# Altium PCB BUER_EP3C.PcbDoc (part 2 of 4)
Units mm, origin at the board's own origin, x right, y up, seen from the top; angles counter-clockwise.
Board outline 150 x 80 mm, 2 copper layers (Top Layer, Bottom Layer), stack 1.571 mm thick; 295 components, 180 nets, 1344 pads, 488 vias.
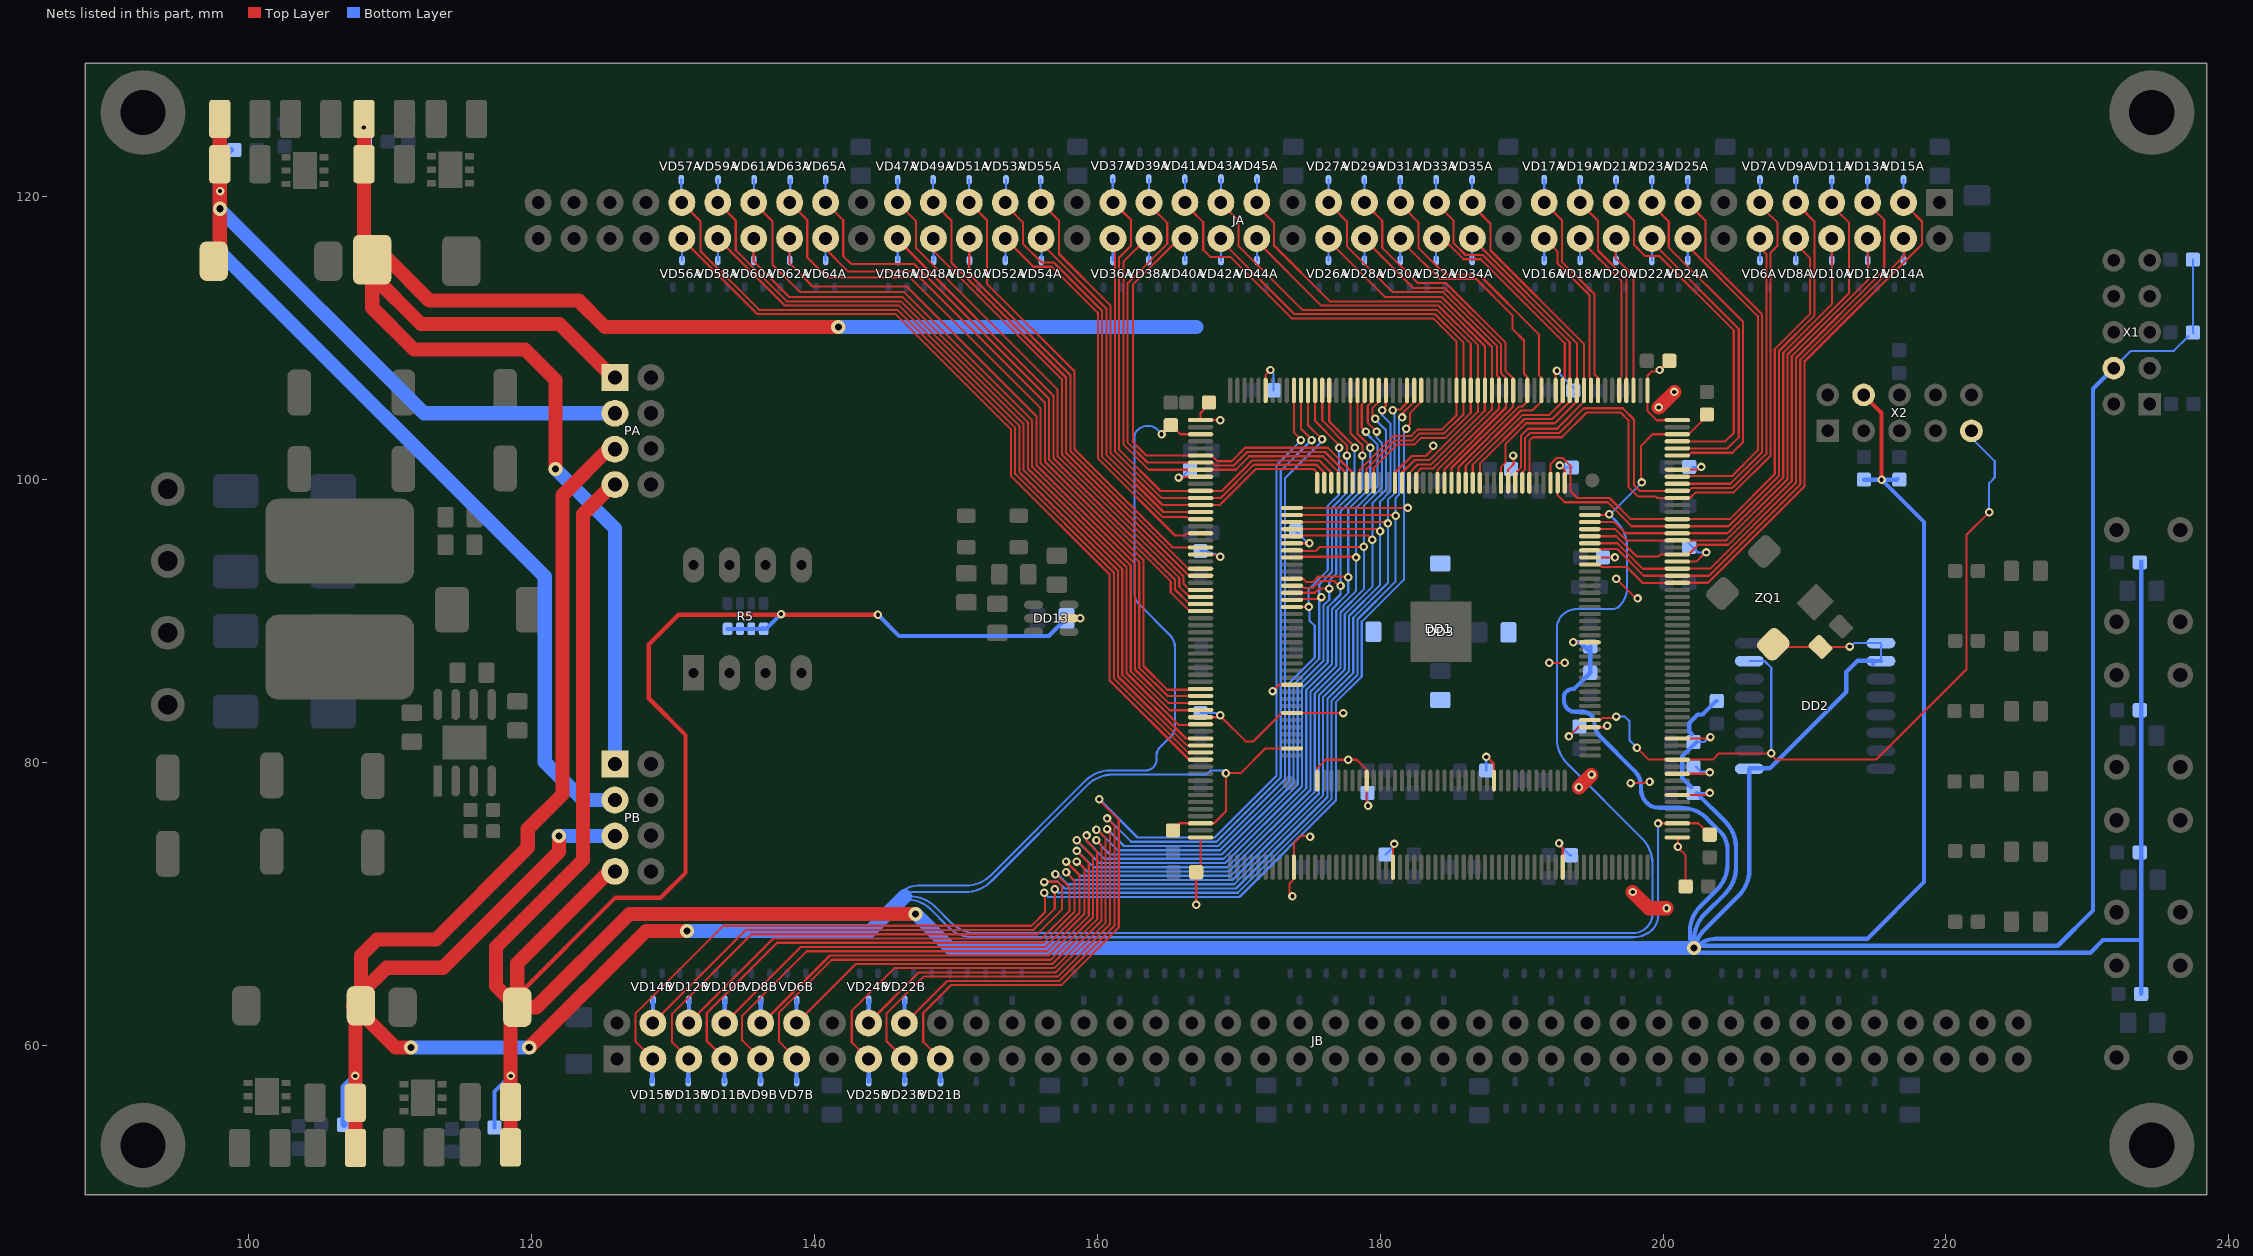
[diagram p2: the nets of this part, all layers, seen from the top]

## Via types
v1: diameter 0.6, hole 0.3, Top Layer to Bottom Layer, tented both sides, 413 vias
v2: diameter 1.4, hole 0.7, Top Layer to Bottom Layer, 32 vias
v3: diameter 1, hole 0.5, Top Layer to Bottom Layer, tented both sides, 19 vias
v4: diameter 0.66, hole 0.33, Top Layer to Bottom Layer, tented top, 16 vias
v5: diameter 0.6, hole 0.3, Top Layer to Bottom Layer, 8 vias

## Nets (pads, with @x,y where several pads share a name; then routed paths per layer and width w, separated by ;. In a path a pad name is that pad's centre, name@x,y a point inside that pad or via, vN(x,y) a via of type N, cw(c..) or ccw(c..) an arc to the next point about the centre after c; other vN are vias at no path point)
1.2V: C21.1 C22.1 C23.1 C24.1 C25.1 C26.1 C27.1 C28.1 C29.1 C30.1 C31.1 C32.1 C34.1 C35.1 C47.1 C75.1 C76.1 C77.1 C78.1 C79.1 C80.1 C81.1 C82.1 C86.1 C87.1 C88.1 C89.1 DD1.1 DD1.10 DD1.40 DD1.53 DD1.60 DD1.61 DD1.74 DD1.115 DD1.121 DD1.129 DD1.140 DD1.163 DD1.180 DD1.190 DD1.204 DD1.228 DD3.5 DD3.29 DD3.37 DD3.45 DD3.61 DD3.78 DD3.102 DD3.109 DD3.116 DD3.134 L1.2 PA.1 PB.1 R6.2 | length 242
  Top Layer w0.15: v1@165.9,100 cw(c166.399,99.501) 166.399,100.207 DD1.129@167.306,100.207 ; v1@167,69.9 C32.1@167,72.25 167.306,72.25 DD1.180@167.306,74.707 ; DD1.163@167.306,83.207 168.507,83.207 v1@168.65,83.35 ; DD1.140@167.306,94.707 168.08,94.707 cw(c168.08,93.83) v1@168.7,94.45 ; DD1.121@167.306,104.157 DD1.121@167.306,104.207 ; C29.1@167.65,105.8 167.65,105.049 167.306,104.705 DD1.121@167.306,104.207 ; v1@168.65,104.15 168.593,104.207 DD1.121@167.306,104.207 ; v1@168.75,83.25 170.5,81.5 171.05,81.5 173.05,83.5 DD3.102@173.775,83.5 v1@177.3,83.5 ; DD1.115@171.906,106.307 171.906,107.406 v1@172.2,107.7 ; DD3.78@173.775,95.5 v1(175,95.5) v1@175.15,95.5 ; v1@173.85,70.5 173.6,70.75 173.6,71.45 173.906,71.756 173.906,74.306 174.4,74.8 v1@175,74.8 ; DD3.109@175.55,78.725 175.55,79.6 176.15,80.2 178.35,80.2 179.05,79.5 DD3.116@179.05,78.725 179.05,77 v1@179.25,76.8 ; DD1.204@180.906,72.607 180.906,74.106 v1@180.95,74.15 ; DD3.61@181.05,99.775 181.05,100.5 182.225,101.675 183.225,101.675 183.75,102.2 v1(183.75,102.4) ; v1@187.55,80.4 188.05,79.9 DD3.134@188.05,78.725 ; DD3.45@189.05,99.775 189.05,100.7 189.45,101.1 v1@189.45,101.75 ; v1@191.9,87.05 v1(191.95,87.05) v1(193.05,87.05) ; DD1.74@192.406,106.307 192.406,107.506 v1@192.6,107.7 ; v1@192.6,74.25 192.906,73.944 DD1.228@192.906,72.607 ; v1(192.7,101) 193.05,100.65 DD3.37@193.05,99.775 ; v1@193.25,81.75 194,82.5 DD3.5@194.825,82.5 195.95,82.5 v1(196.05,82.6) ; DD3.29@194.825,94.5 196.45,94.5 v1@196.5,94.55 ; v1(196.7,93) v1@198.15,91.55 ; v1(197.7,78.55) 198.85,78.55 v1@198.95,78.65 ; C25.1@200.1,108.05 199.7,107.65 199.2,107.65 198.906,107.356 DD1.61@198.906,106.307 198.906,104.844 199.55,104.2 DD1.60@200.4,104.2 ; DD1.10@201.006,79.207 203.207,79.207 v1@203.35,79.35 ; DD1.40@201.006,94.207 202.357,94.207 v1@203,94.85 ; DD1.53@201.006,100.707 202.707,100.707 v1@202.75,100.75 ; DD1.1@201.05,74.7 201.05,74 201.6,73.45 C21.1@201.6,71.25
  Top Layer w1: C34.1@108.175,125.5 C35.1@108.175,122.3 108.175,116.125 L1.2@108.75,115.55 ; L1.2@109,115.3 L1.2@108.75,115.55 ; v3(121.7,100.75) 121.7,107.05 119.55,109.2 111.7,109.2 108.75,112.15 L1.2@108.75,114.45 ; PA.1@125.5,107.5 122,111 112.2,111 L1.2@108.75,114.45 ; v3(141.7,110.8) 125.2,110.8 123.35,112.65 112.8,112.65 109.9,115.55 L1.2@108.75,115.55 ; v1(194.05,78.25) v1@194.9,79.1 ; v1(197.85,70.85) 199,69.7 v1(200.25,69.7) ; v1(199.7,105.1) v1(200.8,106.2) ; L1.2@108.75,114.45 L1.2@108.75,115.55
  Bottom Layer w0.15: v1@165.7,99.9 166.465,100.665 cw(c166.55,100.579) C30.1@166.55,100.7 ; C22.1@167.3,83.5 168.65,83.5 v1@168.75,83.4 ; C31.1@167.3,94.95 167.493,94.95 cw(c167.493,93.243) v1@168.7,94.45 ; v1@172.25,107.7 172.47,107.48 C28.1@172.47,106.315 ; C81.1@174.05,96.35 174.8,95.6 v1@174.85,95.6 ; C75.1@179.1,77.85 179.1,77.15 v1@179.15,77.1 ; C23.1@180.4,73.5 180.95,74.05 v1@180.85,74.15 ; C76.1@187.5,79.45 v1(187.5,80.4) ; v1(192.5,107.7) v1@192.5,107.788 ; v1@192.55,107.6 192.575,107.6 193.875,106.3 cw(c193.453,106.3) C27.1@193.751,106.001 ; v1@192.6,74.25 193.4,73.45 C82.1@193.5,73.45 ; v1(192.7,101) 192.85,100.85 C79.1@193.55,100.85 ; v1@193.25,81.75 193.3,81.75 C77.1@194.1,82.55 ; C78.1@195.75,94.5 196.5,94.5 v1@196.55,94.55 ; C24.1@201.744,95.581 202.475,94.85 v1(203.05,94.85) ; C26.1@202.075,100.9 v1(202.7,100.9) ; C47.1@202.325,79.7 202.375,79.65 202.675,79.35 v1@203.35,79.35
  Bottom Layer w0.5: R6.2@108.1,123.95 108.15,124 v1(108.15,124.9)
  Bottom Layer w1: v3(121.7,100.75) 125.91,96.54 PB.1@125.91,79.89 ; v3(141.7,110.8) 167,110.8
  other v1: 167,69.95 173.8,70.55 201.05,74.05 181,74.25 192.65,74.3 175.05,74.75 179.15,76.95 199.05,78.65 194.95,79.15 203.3,79.3 177.75,80.2 193.35,81.85 168.7,83.35 177.4,83.5 198.2,91.6 196.6,94.5 168.7,94.55 165.75,100.15 189.4,101.7 168.7,104.2 172.25,107.75 199.75,107.75
1.8V: C43.1 C44.1 L2.2 PA.3 PB.3 R17.2 | length 101.4
  Top Layer w1: L2.2@97.8,115.9 97.975,116.075 C44.1@97.975,122.3 C43.1@97.975,125.5
  Bottom Layer w0.4: v1(98,120.4) 98,122.525 R17.2@98.775,123.3
  Bottom Layer w1: v3(98,119.15) v3@98,119.1 ; PA.3@125.9,104.69 112.41,104.69 v3@98,119.1 ; PB.3@125.91,77.35 123.65,77.35 120.95,80.05 120.95,93.15 98,116.1 v3@98,119.1
2.5V: C17.1 C18.1 C19.1 C20.1 C52.1 C53.1 DD1.3 DD1.58 DD1.123 DD1.178 DD3.35 DD3.107 L4.2 PA.5 PB.5 R8.2 | length 385.5
  Top Layer w0.15: v1@164.6,103.2 C19.1@165.165,103.765 ; C19.1@165.165,103.765 ccw(c165.079,103.85) C19.1@165.2,103.85 ; C19.1@165.25,103.45 165.65,103.45 165.893,103.207 DD1.123@167.306,103.207 ; C20.1@165.6,75.5 165.807,75.707 DD1.178@167.306,75.707 168.257,75.707 169.1,76.55 169.1,79.2 169.15,79.25 170.149,79.25 171.899,81 DD3.107@173.2,81 ; DD3.35@194.825,97.5 v1@196.001,97.5 ; v1@198.45,99.85 198.45,102.4 199.257,103.207 201.807,103.207 C18.1@202.8,104.2 ; v1@199.65,75.65 199.707,75.707 DD1.3@201.006,75.707 ; DD1.3@201,75.7 DD1.3@201.006,75.707 ; C17.1@202.9,75.3 202.493,75.707 DD1.3@201.006,75.707
  Top Layer w1: L4.2@107.4,62.75 107.575,62.575 C53.1@107.575,52.75 ; v3(111.5,59.85) 110.4,59.85 107.95,62.3 L4.2@107.95,62.8 L4.2@107.95,63.7 ; v3(119.85,59.85) 128.1,68.1 v3(131,68.1) ; v3@121.95,74.7 121.95,73.7 113.75,65.5 109.75,65.5 L4.2@107.95,63.7 ; PA.5@125.5,102.2 122.2,98.9 122.2,77.75 119.75,75.3 119.75,74 113.25,67.5 109.1,67.5 107.95,66.35 L4.2@107.95,63.7
  Bottom Layer w0.15: 146.2,70.85 cw(c147.286,69.764) 147.286,71.3 150.698,71.3 ccw(c150.698,73.84) 152.494,72.044 159.156,78.706 cw(c160.952,76.91) 160.952,79.45 163.45,79.45 ccw(c163.45,80.174) 163.962,79.662 ccw(c163.388,80.236) 164.2,80.236 164.2,80.496 cw(c165.054,80.496) 164.45,81.1 165.217,81.867 ccw(c164.534,82.55) 165.5,82.55 165.5,88.155 ccw(c164.305,88.155) 165.15,89 162.897,91.253 cw(c163.495,91.85) 162.65,91.85 162.65,103.088 cw(c163.162,103.088) 162.8,103.45 162.832,103.482 cw(c163.6,102.714) 163.6,103.8 cw(c163.6,102.834) 164.283,103.517 v1@164.5,103.3 ; 146.55,70.65 cw(c147.033,70.167) 147.033,70.85 150.698,70.85 ccw(c150.698,73.39) 152.494,71.594 159.306,78.406 cw(c161.102,76.61) 161.102,79.15 ; 146.65,70.3 cw(c146.65,68.127) 148.186,69.664 149.456,68.394 ccw(c151.252,70.19) 151.252,67.65 197.922,67.65 ccw(c197.922,69.528) 199.25,68.2 ccw(c198.284,69.166) 199.65,69.166 v1(199.65,75.7) ; 146.65,70.55 146.748,70.55 cw(c146.748,68.01) 148.544,69.806 149.656,68.694 ccw(c151.452,70.49) 151.452,67.95 197.864,67.95 ccw(c197.864,69.366) 198.865,68.365 ccw(c197.934,69.295) 199.25,69.295 199.25,72.848 ccw(c196.71,72.848) 198.506,74.644 193.244,79.906 cw(c195.04,81.702) 192.5,81.702 192.5,89.543 cw(c193.724,89.543) 192.859,90.409 cw(c193.924,89.343) 193.924,90.85 196.417,90.85 ccw(c196.417,91.533) 196.9,91.05 ccw(c195.572,92.378) 197.45,92.378 197.45,93.35 ; 161.1,79.15 167.719,79.15 168.019,79.45 168.9,79.45 v1(169.1,79.25) ; v1(164.55,103.2) v1@164.55,103.25 ; v1@168.95,79.15 v1@169,79.2 ; v1(196.2,97.55) 196.706,97.044 cw(c194.91,95.248) 197.45,95.248 197.45,93.352 ; v1@196.3,97.6 v1@198.45,99.75
  Bottom Layer w0.5: R8.2@106.75,54.4 106.75,57.05 v1(107.55,57.85)
  Bottom Layer w1: v3(111.5,59.85) v3(119.85,59.85) ; v3@121.94,74.81 PB.5@125.91,74.81 ; v3@130.95,68.1 143.95,68.1 146.397,70.547
  other v1: 198.5,99.8
  other v3: 121.95,74.8
3.3V: C1.1 C2.1 C45.1 C55.1 C56.1 C58.1 C85.1 DD1.7 DD1.15 DD2.1 DD2.2 DD2.9 DD3.17 DD13.5 L5.2 PA.7 PB.7 R1.2 R2.2 R3.2 R5.5 R5.6 R5.7 R5.8 R10.2 R14.2 R15.2 R19.2 R20.2 R21.2 R22.2 R23.2 X1.4 X2.4 ZQ1.4 | length 519.5
  Top Layer w0.15: v1@193.7,88.5 DD3.17@194.825,88.5 ; DD1.7@201.006,77.707 203.057,77.707 v1@203.3,77.95 ; DD1.15@201.006,81.707 203.257,81.707 v1(203.35,81.8) ; ZQ1.4@208,88.3 208.125,88.175 C58.1@211.125,88.175 v1@213.225,88.175
  Top Layer w0.3: L5.2@119,62.7 119,63.5 125.95,70.45 129.15,70.45 130.9,72.2 130.9,81.95 128.3,84.55 128.3,88.35 130.4,90.45 v1@144.4,90.45 ; DD13.5@158,90.2 v1(158.8,90.2) ; X2.4@214.18,105.99 215.45,104.72 v1(215.45,100)
  Top Layer w1: C55.1@118.526,52.8 L5.2@118.526,62.574 ; PB.7@125.55,72.35 119,65.8 L5.2@119,62.7 ; PA.7@125.6,99.5 123.65,97.55 123.65,73.1 117.5,66.95 117.5,64.2 L5.2@119,62.7 ; v3(147.15,69.3) 126.95,69.3 120.35,62.7 L5.2@119,62.7
  Bottom Layer w0.15: C1.1@202.325,77.85 202.375,77.85 v1(203.3,77.85) ; C2.1@202.375,81.45 202.9,81.45 v1@203.3,81.85 ; v1@213.25,88.2 213.495,88.445 DD2.1@215.4,88.445 ; DD2.2@215.4,87.175 215.4,88.25 DD2.1@215.45,88.3 ; X1.4@231.86,107.88 233.08,109.1 236.1,109.1 R2.2@237.15,110.15 ; R1.2@237.45,115.55 R2.2@237.45,110.4 R2.2@237.5,110.35
  Bottom Layer w0.3: R10.2@117.4,54.2 117.4,56.75 v1@118.45,57.8 ; R5.8@133.875,89.45 R5.7@134.75,89.45 R5.6@135.55,89.45 136.3,89.45 R5.5@136.35,89.5 ; R5.5@136.425,89.45 136.6,89.45 v1(137.65,90.5) ; v1(144.5,90.45) 146,88.95 156.575,88.95 C85.1@157.825,90.2 v1@158.75,90.2 ; v1@193.75,88.5 194.15,88.5 194.675,87.975 C45.1@194.85,87.975 ; R19.2@194.85,86.35 193.735,85.235 cw(c193.65,85.321) 193.65,85.2 ccw(c193.65,84.476) 193.138,84.988 ccw(c193.471,84.655) 193,84.655 193,84.404 ccw(c193.854,84.404) 193.25,83.8 ccw(c193.733,84.283) 193.733,83.6 194.296,83.6 cw(c194.296,82.746) 194.9,83.35 cw(c194.296,82.746) 195.15,82.746 ccw(c196.349,82.746) 195.501,81.899 197.99,79.41 cw(c196.881,78.3) 198.45,78.3 198.45,78.116 ccw(c199.816,78.116) 198.85,77.15 ccw(c199.695,77.995) 199.695,76.8 201.25,76.8 ; R19.2@194.85,86.4 C45.1@194.85,87.975 ; C45.1@194.85,88.2 C45.1@194.85,87.975 ; 201.298,76.8 cw(c201.298,74.26) 203.094,76.056 204.055,75.095 cw(c202.86,73.9) 204.55,73.9 204.55,72.802 cw(c202.01,72.802) 203.806,71.006 202.642,69.842 ccw(c204.435,68.05) 201.9,68.05 201.9,67.654 ccw(c202.754,67.654) v3@202.05,67.17 ; C1.1@202,78.25 201.35,78.9 201.35,80.425 C2.1@202.375,81.45 ; v3@202.05,67.05 v3@202.05,67.17 ; v3@202.05,67.3 v3@202.05,67.17 ; 202.05,82 201.85,82.2 201.85,82.8 202.45,83.4 202.8,83.4 203.75,84.35 R3.2@203.8,84.35 ; v3@202.1,66.9 202.45,66.55 230.2,66.55 231.1,67.45 233.8,67.45 ; v3@202.15,67.05 cw(c202.754,67.654) v3@202.05,67.17 ; v3@202.2,67.05 202.2,67.498 cw(c204.74,67.498) 202.944,69.294 204.406,70.756 ccw(c202.61,72.552) 205.15,72.552 205.15,74.023 ccw(c202.61,74.023) 204.406,75.819 C1.1@202.375,77.85 ; v3@202.3,66.9 v3@202.351,66.951 ; v3@202.3,67 202.35,67.05 v3@202.357,67.05 ; v3@202.3,67.05 v3@202.364,67.114 ; v3@202.35,66.9 cw(c204.04,66.9) v3@202.351,66.951 ; v3@202.45,67.15 202.4,67.15 v3@202.364,67.114 ; R14.2@214.2,100 v1(215.45,100) ; DD2.2@214.525,87.175 DD2.2@215.4,87.175 ; DD2.2@214.7,87.2 213.75,87.2 212.95,86.4 212.95,85 207.55,79.6 206.145,79.6 DD2.9@206.1,79.555 206.1,72.402 cw(c203.56,72.402) 205.356,70.606 202.845,68.095 ccw(c204.04,66.9) v3@202.364,67.114 ; DD2.2@214.85,86.96 DD2.2@214.85,87.2 ; R15.2@216.55,100.05 216.5,100 v1(215.45,100) ; X1.4@231.86,107.88 230.4,106.42 230.4,69.55 227.9,67.05 v3@202.453,67.05 ; R23.2@233.8,63.65 233.8,67.45 ; R20.2@233.8,94.2 233.8,67.45 ; v3@202.351,66.951 cw(c204.04,66.9) v3@202.357,67.05 ; v3@202.351,66.951 202.384,66.984 cw(c203.75,65.619) v3@202.453,67.05 ; v3@202.357,67.05 cw(c204.04,66.9) v3@202.364,67.114 ; v3@202.357,67.05 v3@202.453,67.05 ; v3@202.453,67.05 cw(c203.75,65.619) 203.75,67.55 214.45,67.55 218.45,71.55 218.45,97 v1(215.45,100)
  Bottom Layer w1: v3(147.15,69.3) 147.2,69.3 149.6,66.9 v3@202.1,66.9
  other v1: 118.55,57.85 213.2,88.2 193.65,88.5
  other v3: 202.2,66.9
A0: DD1.37 DD3.28 JA.3 VD15A.3 | length 42.3
  Top Layer w0.15: DD3.28@195.5,94 195.675,93.825 197.425,93.825 198.55,92.7 DD1.37@200.4,92.7 ; DD1.37@201.006,92.707 203.177,92.707 210,99.53 210,108.35 218.3,116.65 218.3,118.25 JA.3@217.4,119.15
  Bottom Layer w0.15: JA.3@217,119.6 VD15A.3@217,121.2
A1: DD1.38 DD3.30 JA.4 VD14A.3 | length 39.1
  Top Layer w0.15: DD3.30@195.5,95 195.6,95.1 196.75,95.1 198.643,93.207 DD1.38@201.006,93.207 203.252,93.207 209.7,99.654 209.7,108.474 217.05,115.824 JA.4@217.05,117.05
  Bottom Layer w0.15: VD14A.3@217,115.5 JA.4@217,116.5
A2: DD1.39 DD3.31 JA.5 VD13A.3 | length 41.1
  Top Layer w0.15: DD3.31@194.825,95.5 196.774,95.5 198.574,93.7 DD1.39@200.5,93.7 ; DD1.39@201.006,93.707 203.328,93.707 209.4,99.779 209.4,108.599 215.635,114.834 215.635,118.365 JA.5@214.9,119.1
  Bottom Layer w0.15: JA.5@214.45,119.65 214.462,119.662 VD13A.3@214.462,121.2
A3: DD1.41 DD3.32 JA.6 VD12A.3 | length 36.4
  Top Layer w0.15: DD3.32@194.825,96 196.699,96 198.124,94.575 199.675,94.575 199.8,94.7 DD1.41@200.55,94.7 ; DD1.41@201.006,94.707 DD1.41@201.013,94.7 ; DD1.41@201.8,94.7 202.5,95.4 204.597,95.4 209.1,99.903 209.1,108.723 214.5,114.123 JA.6@214.5,116.75
  Bottom Layer w0.15: VD12A.3@214.462,115.5 214.462,116.812 JA.6@214.55,116.9
A4: DD1.43 DD3.33 JA.7 VD11A.3 | length 38.2
  Top Layer w0.15: DD3.33@194.825,96.5 196.623,96.5 197.423,95.7 DD1.43@200.55,95.7 ; DD1.43@201.006,95.707 204.48,95.707 208.8,100.027 208.8,108.847 213.15,113.197 213.15,118.15 JA.7@212.2,119.1
  Bottom Layer w0.15: JA.7@211.9,119.95 211.925,119.975 VD11A.3@211.925,121.2
A5: DD1.44 DD3.34 JA.8 VD10A.3 | length 34.4
  Top Layer w0.15: DD3.34@195.35,97 196.547,97 197.34,96.207 DD1.44@201.006,96.207 204.555,96.207 208.5,100.151 208.5,108.971 211.95,112.421 JA.8@211.95,116.8
  Bottom Layer w0.15: VD10A.3@211.925,115.5 211.925,116.475 JA.8@212.1,116.65
A6: DD1.45 DD3.38 JA.9 VD9A.3 | length 40.1
  Top Layer w0.15: DD3.38@192.55,99.1 192.55,98.9 193.05,98.4 196.092,98.4 197.786,96.707 204.631,96.707 208.2,100.276 208.2,109.096 210.7,111.596 210.7,118.25 JA.9@209.75,119.2
  Bottom Layer w0.15: JA.9@209.25,119.75 209.387,119.887 VD9A.3@209.387,121.2
A7: DD1.46 DD3.39 JA.10 VD8A.3 | length 40.1
  Top Layer w0.15: DD3.39@192.05,100.4 192.05,101.1 192.475,101.525 192.917,101.525 193.45,100.992 193.45,99.2 193.95,98.7 196.217,98.7 197.71,97.207 204.707,97.207 207.9,100.4 207.9,109.22 210.4,111.72 210.4,115.65 JA.10@209.35,116.7
  Bottom Layer w0.15: VD8A.3@209.387,115.5 209.387,116.637 JA.10@209.6,116.85
A8: DD1.49 DD3.42 JA.11 VD7A.3 | length 45.5
  Top Layer w0.15: DD3.42@190.55,100.3 190.55,102.75 190.8,103 192.85,103 194.6,104.75 197,104.75 197.55,104.2 197.55,99.5 198.25,98.8 199.5,98.8 199.6,98.7 DD1.49@200.25,98.7 ; DD1.49@201.006,98.707 201.013,98.7 201.9,98.7 202.3,99.1 205,99.1 207.6,101.7 207.6,116.05 208.1,116.55 208.1,118.15 JA.11@207.2,119.05
  Bottom Layer w0.15: JA.11@206.85,119.7 VD7A.3@206.85,121.2
A9: DD1.50 DD3.43 JA.12 VD6A.3 | length 43.7
  Top Layer w0.15: DD3.43@190.05,99.775 190.05,100.526 190.25,100.726 190.25,102.95 190.6,103.3 192.65,103.3 194.4,105.05 197.15,105.05 197.95,104.25 197.95,99.6 198.35,99.2 DD1.50@200.95,99.2 ; DD1.50@201.006,99.207 201.807,99.207 202,99.4 204.876,99.4 207.3,101.824 207.3,115.95 206.9,116.35 JA.12@206.9,116.55
  Bottom Layer w0.15: VD6A.3@206.85,115.5 JA.12@206.85,116.95
A10: DD1.51 JA.15 VD25A.3 | length 27.7
  Top Layer w0.15: DD1.51@201.006,99.707 204.758,99.707 207,101.949 207,111.674 203,115.674 203,118.3 JA.15@202.15,119.15
  Bottom Layer w0.15: JA.15@201.7,119.65 201.75,119.7 VD25A.3@201.75,121.2
A11: DD1.52 JA.16 VD24A.3 | length 24.3
  Top Layer w0.15: DD1.52@201.45,100.25 204.877,100.25 206.7,102.073 206.7,111.55 201.76,116.49 JA.16@201.76,117.05
  Bottom Layer w0.15: JA.16@201.7,116.8 201.75,116.75 VD24A.3@201.75,115.5
A12: DD1.55 JA.17 VD23A.3 | length 25.5
  Top Layer w0.15: JA.17@199.4,119.25 200.4,118.25 200.4,116.4 205.65,111.15 205.65,102.65 204.9,101.9 202,101.9 201.8,101.7 201.013,101.7 DD1.55@201.006,101.707
  Bottom Layer w0.15: JA.17@199.05,120 199.212,120.162 VD23A.3@199.212,121.2
A13: DD1.56 JA.18 VD22A.3 | length 22.5
  Top Layer w0.15: JA.18@199.65,116.7 199.65,116.35 205.35,110.65 205.35,103 204.557,102.207 DD1.56@201.006,102.207
  Bottom Layer w0.15: VD22A.3@199.212,115.5 199.212,117.012 JA.18@199.4,117.2
A14: DD1.57 JA.19 VD21A.3 | length 25.3
  Top Layer w0.15: JA.19@197.1,119.15 197.95,118.3 197.95,116.6 198.75,115.8 199.75,115.8 205,110.55 205,103.3 204.407,102.707 DD1.57@201.006,102.707
  Bottom Layer w0.15: JA.19@196.65,119.9 196.675,119.925 VD21A.3@196.675,121.2
A15: DD1.63 JA.20 VD20A.3 | length 12.5
  Top Layer w0.15: JA.20@197,116.55 196.65,116.2 196.65,115.65 197.906,114.394 DD1.63@197.906,106.307
  Bottom Layer w0.15: VD20A.3@196.675,115.5 196.675,117.025 JA.20@196.7,117.05
A16: DD1.64 JA.21 VD19A.3 | length 15.4
  Top Layer w0.15: JA.21@194.6,119.1 195.4,118.3 195.4,116.2 197.406,114.194 DD1.64@197.406,106.307
  Bottom Layer w0.15: JA.21@194.1,119.75 194.137,119.787 VD19A.3@194.137,121.2
A17: DD1.65 JA.22 VD18A.3 | length 13.1
  Top Layer w0.15: JA.22@194.3,116.8 197.075,114.025 197.075,107.275 196.906,107.106 DD1.65@196.906,106.307
  Bottom Layer w0.15: JA.22@193.95,116.85 194.137,116.663 VD18A.3@194.137,115.5
A18: DD1.68 JA.23 VD17A.3 | length 15.8
  Top Layer w0.15: JA.23@191.9,119.3 192.85,118.35 192.85,115.4 195.15,113.1 195.15,107.45 195.406,107.194 DD1.68@195.406,106.307
  Bottom Layer w0.15: VD17A.3@191.6,121.2 191.6,119.95 JA.23@191.65,119.9
A19: DD1.69 JA.24 VD16A.3 | length 12.8
  Top Layer w0.15: JA.24@191.95,116.7 192.55,116.1 192.55,115.276 194.8,113.026 194.8,107.2 194.906,107.094 DD1.69@194.906,106.307
  Bottom Layer w0.15: JA.24@191.45,116.65 191.6,116.5 VD16A.3@191.6,115.5
A20: DD1.70 DD3.44 JA.27 VD35A.3 | length 26.4
  Top Layer w0.15: JA.27@186.95,118.95 187.8,118.1 187.8,116.2 194.406,109.594 DD1.70@194.406,106.307 ; DD3.44@189.55,99.775 189.55,100.45 189.95,100.85 189.95,103.1 190.45,103.6 192.5,103.6 194.4,105.5 DD1.70@194.4,105.55
  Bottom Layer w0.15: VD35A.3@186.5,121.2 186.5,119.85 JA.27@186.75,119.6
A21: DD1.71 DD3.46 JA.28 VD34A.3 | length 24.2
  Top Layer w0.15: JA.28@186.9,116.55 186.999,116.55 193.906,109.642 DD1.71@193.906,106.307 ; DD3.46@188.55,99.775 188.55,100.9 188.85,101.2 188.85,102.5 190.332,103.982 192.362,103.982 193.88,105.5 DD1.71@193.9,105.5
  Bottom Layer w0.15: VD34A.3@186.5,115.5 186.5,117.25 JA.28@186.55,117.3
A22: DD1.72 DD3.49 JA.29 VD33A.3 | length 28
  Top Layer w0.15: JA.29@184.45,119.05 185.2,118.3 185.2,116.708 186.033,115.875 187.249,115.875 193.406,109.718 DD1.72@193.406,106.307 ; DD3.49@187.05,99.775 187.05,101.124 190.207,104.282 192.162,104.282 193.4,105.52 DD1.72@193.4,105.6
  Bottom Layer w0.15: VD33A.3@183.962,121.2 183.962,120.188 JA.29@184.1,120.05
A23: DD1.73 DD3.50 JA.30 VD32A.3 | length 26.1
  Top Layer w0.15: JA.30@184.25,116.6 184.884,116.6 185.909,115.575 187.125,115.575 193.05,109.65 193.05,107.25 192.906,107.106 DD1.73@192.906,106.307 ; DD3.50@186.55,99.775 186.55,101.049 190.083,104.582 191.962,104.582 192.9,105.52 DD1.73@192.9,105.7
  Bottom Layer w0.15: VD32A.3@183.962,115.5 183.962,116.812 JA.30@184,116.85
A24: DD1.76 DD3.51 JA.31 VD31A.3 | length 27.8
  Top Layer w0.15: JA.31@181.9,119 182.7,118.2 182.7,116.4 184.6,114.5 186.992,114.5 191.225,110.267 191.225,107.375 191.406,107.194 DD1.76@191.406,106.307 ; DD3.51@186.05,99.775 186.05,100.973 189.959,104.882 190.762,104.882 191.45,105.57 DD1.76@191.45,105.6
  Bottom Layer w0.15: VD31A.3@181.425,121.2 181.425,120.075 JA.31@181.5,120
A25: DD1.78 DD3.52 JA.32 VD30A.3 | length 24.4
  Top Layer w0.15: JA.32@181.75,116.65 184.2,114.2 186.776,114.2 189.35,111.626 189.35,110.658 190.175,109.833 190.175,107.483 190.406,107.251 DD1.78@190.406,106.307 ; DD3.52@185.55,99.775 185.55,100.897 189.835,105.182 190.062,105.182 190.4,105.52 DD1.78@190.4,105.6
  Bottom Layer w0.15: VD30A.3@181.425,115.5 181.425,116.475 JA.32@181.45,116.5
A26: DD1.80 DD3.53 JA.33 VD29A.3 | length 27.5
  Top Layer w0.15: JA.33@179.25,119.2 180.15,118.3 180.15,116.4 182.65,113.9 184.65,113.9 188.85,109.7 188.85,107.7 189.4,107.15 189.4,106.313 DD1.80@189.406,106.307 ; DD3.53@185.05,99.775 185.05,100.821 189.4,105.171 DD1.80@189.4,105.8
  Bottom Layer w0.15: VD29A.3@178.887,121.2 178.887,119.863 JA.33@178.9,119.85
A27: DD1.81 DD3.54 JA.34 VD28A.3 | length 25.2
  Top Layer w0.15: JA.34@178.9,117 182.35,113.55 184.576,113.55 188.55,109.576 188.55,107.5 188.906,107.144 DD1.81@188.906,106.307 ; DD3.54@184.55,99.775 184.55,100.746 188.9,105.096 DD1.81@188.9,105.85
  Bottom Layer w0.15: JA.34@178.8,116.6 178.887,116.513 VD28A.3@178.887,115.5
A28: DD1.82 DD3.55 JA.35 VD27A.3 | length 29.2
  Top Layer w0.15: JA.35@176.75,119.15 177.65,118.25 177.65,116.5 180.9,113.25 184.451,113.25 188.25,109.451 188.25,107.376 188.406,107.219 DD1.82@188.406,106.307 ; DD3.55@184.05,99.775 184.05,100.67 188.4,105.02 DD1.82@188.4,105.9
  Bottom Layer w0.15: JA.35@176.35,119.65 VD27A.3@176.35,121.2
A29: DD1.83 DD3.58 JA.36 VD26A.3 | length 27.9
  Top Layer w0.15: JA.36@176.15,117.1 180.35,112.9 184.377,112.9 187.906,109.371 DD1.83@187.906,106.307 ; DD3.58@182.55,99.775 182.55,100.45 182.875,100.775 183.731,100.775 187.9,104.944 DD1.83@187.9,105.7
  Bottom Layer w0.15: VD26A.3@176.35,115.5 176.35,116.7 JA.36@176.4,116.75
A30: DD1.84 DD3.59 JA.39 VD45A.3 | length 33.5
  Top Layer w0.15: JA.39@171.65,119 172.5,118.15 172.5,116.55 176.45,112.6 184.253,112.6 187.406,109.447 DD1.84@187.406,106.307 ; DD3.59@182.05,99.775 182.05,100.45 182.675,101.075 183.607,101.075 187.4,104.868 DD1.84@187.4,105.55
  Bottom Layer w0.15: VD45A.3@171.3,121.25 171.3,120.1 JA.39@171.35,120.05
A31: DD1.85 DD3.60 JA.40 VD44A.3 | length 32
  Top Layer w0.15: JA.40@171.25,117.05 171.25,116.9 175.85,112.3 184.129,112.3 186.906,109.522 DD1.85@186.906,106.307 186.906,104.799 183.482,101.375 182.425,101.375 181.55,100.5 DD3.60@181.55,100.4
  Bottom Layer w0.15: JA.40@171.25,116.65 171.3,116.6 VD44A.3@171.3,115.5
A32: DD1.86 DD3.64 JA.41 VD43A.3 | length 37.5
  Top Layer w0.15: JA.41@169,119.3 170,118.3 170,116.5 174.5,112 184.004,112 186.406,109.598 DD1.86@186.406,106.307 186.406,104.723 184.633,102.95 182.899,102.95 182.424,102.475 181.175,102.475 179.55,100.85 DD3.64@179.55,100.4
  Bottom Layer w0.15: JA.41@168.55,120.05 168.75,120.25 VD43A.3@168.75,121.25
A33: DD1.87 DD3.65 JA.42 VD42A.3 | length 34.7
  Top Layer w0.15: JA.42@168.9,116.75 173.95,111.7 183.88,111.7 185.906,109.674 DD1.87@185.906,106.307 ; DD3.65@179.05,99.775 179.05,100.774 181.051,102.775 182.299,102.775 182.774,103.25 184.509,103.25 185.9,104.641 DD1.87@185.9,105.6
  Bottom Layer w0.15: VD42A.3@168.75,115.5 JA.42@168.75,116.5
A34: DD1.88 DD3.66 JA.43 VD41A.3 | length 39.4
  Top Layer w0.15: JA.43@166.6,119.1 167.5,118.2 167.5,116.25 168,115.75 169.4,115.75 173.75,111.4 183.756,111.4 185.406,109.75 DD1.88@185.406,106.307 185.406,104.572 184.385,103.55 182.65,103.55 182.175,103.075 180.926,103.075 178.55,100.699 DD3.66@178.55,100.2
  Bottom Layer w0.15: VD41A.3@166.2,121.25 166.2,120 JA.43@166.3,119.9
A35: DD1.126 DD3.67 JA.44 VD40A.3 | length 34.6
  Top Layer w0.15: JA.44@166.2,117.05 165.8,117.05 162.525,113.775 162.525,102.663 163.488,101.7 DD1.126@166.9,101.7 ; DD1.126@167.306,101.707 DD1.126@167.313,101.7 ; DD1.126@167.9,101.7 168.1,101.7 168.5,101.3 169.5,101.3 170.45,102.25 176.3,102.25 178.05,100.5 DD3.67@178.05,99.775 DD3.67@178.05,99.7
  Bottom Layer w0.15: VD40A.3@166.2,115.5 166.2,116.7 JA.44@166.4,116.9
A36: DD1.127 DD3.68 JA.45 VD39A.3 | length 36.5
  Top Layer w0.15: JA.45@164,119.1 164.95,118.15 164.95,116.678 162.15,113.878 162.15,102.614 163.557,101.207 DD1.127@167.306,101.207 ; DD1.127@168.15,101.2 168.35,101 169.65,101 170.6,101.95 176.1,101.95 177.55,100.5 DD3.68@177.55,99.775
  Bottom Layer w0.15: VD39A.3@163.65,121.25 163.65,119.8 JA.45@163.7,119.75
A37: DD1.128 DD3.69 JA.46 VD38A.3 | length 33.9
  Top Layer w0.15: JA.46@163.66,117.05 163.5,117.05 161.85,115.4 161.85,102.49 163.64,100.7 169.799,100.7 170.749,101.65 175.95,101.65 177.05,100.55 DD3.69@177.05,100.4
  Bottom Layer w0.15: VD38A.3@163.65,115.5 163.65,116.75 JA.46@163.85,116.95
A38: DD1.131 DD3.70 JA.47 VD37A.3 | length 37.4
  Top Layer w0.15: JA.47@161.65,119.1 162.4,118.35 162.4,116.55 161.55,115.7 161.55,102.121 164.471,99.2 168.801,99.2 170.951,101.35 175.7,101.35 176.55,100.5 DD3.70@176.55,99.775
  Bottom Layer w0.15: VD37A.3@161.1,121.25 161.1,119.7 JA.47@161.15,119.65
A39: DD1.132 DD3.71 JA.48 VD36A.3 | length 33.4
  Top Layer w0.15: JA.48@161.15,116.65 161.25,116.55 161.25,108.477 161.25,101.997 164.54,98.707 DD1.132@167.306,98.707 ; DD1.132@167.9,98.7 168.726,98.7 171.076,101.05 175.5,101.05 176.05,100.5 DD3.71@176.05,99.775
  Bottom Layer w0.15: VD36A.3@161.1,115.5 JA.48@161.1,116.7
A40: DD1.133 DD3.72 JA.51 VD55A.3 | length 38
  Top Layer w0.15: JA.51@156.45,119.15 157.3,118.3 157.3,115.95 160.95,112.3 160.95,108.601 160.95,101.873 164.616,98.207 DD1.133@167.306,98.207 ; DD1.133@167.85,98.2 168.65,98.2 171.2,100.75 175.3,100.75 175.55,100.5 DD3.72@175.55,99.775
  Bottom Layer w0.15: JA.51@155.9,119.8 156,119.9 VD55A.3@156,121.2
A41: DD1.134 JA.52 VD54A.3 | length 26.3
  Top Layer w0.15: JA.52@156.25,116.7 156.25,116.5 160.65,112.1 160.65,101.749 164.692,97.707 DD1.134@167.306,97.707
  Bottom Layer w0.15: VD54A.3@156.05,115.5 JA.52@156.05,116.65
A42: DD1.135 JA.53 VD53A.3 | length 29.8
  Top Layer w0.15: JA.53@153.7,119.25 154.75,118.2 154.75,116.678 156.078,115.35 156.924,115.35 160.35,111.924 160.35,101.624 164.624,97.35 166.35,97.35 DD1.135@166.5,97.2 ; DD1.135@167.3,97.2 DD1.135@167.306,97.207
  Bottom Layer w0.15: JA.53@153.5,120.25 153.55,120.3 VD53A.3@153.55,121.2
A43: DD1.137 JA.54 VD52A.3 | length 29.1
  Top Layer w0.15: JA.54@153.5,117.05 155.5,115.05 156.8,115.05 160.05,111.8 160.05,101.5 165.5,96.05 166.2,96.05 166.35,96.2 DD1.137@166.65,96.2
  Bottom Layer w0.15: VD52A.3@153.512,115.5 153.512,116.562 JA.54@153.55,116.6
A44: DD1.139 JA.55 VD51A.3 | length 32.9
  Top Layer w0.15: JA.55@151.45,119.1 152.2,118.35 152.2,113.85 158.4,107.65 158.4,102.15 165.343,95.207 DD1.139@167.306,95.207
  Bottom Layer w0.15: JA.55@150.95,119.9 VD51A.3@150.95,121.2
A45: DD1.142 JA.56 VD50A.3 | length 31.1
  Top Layer w0.15: JA.56@150.96,117.05 150.96,114.54 158.1,107.4 158.1,102.026 166.426,93.7 DD1.142@166.6,93.7
  Bottom Layer w0.15: JA.56@150.95,116.7 150.975,116.675 VD50A.3@150.975,115.5
A46: DD1.143 JA.57 VD49A.3 | length 35.2
  Top Layer w0.15: JA.57@148.42,119.59 149.7,118.31 149.7,115.324 157.8,107.224 157.8,101.901 166.551,93.15 DD1.143@166.7,93.15
  Bottom Layer w0.15: VD49A.3@148.4,121.2 148.4,120.15 JA.57@148.45,120.1
A47: DD1.145 JA.58 VD48A.3 | length 34
  Top Layer w0.15: JA.58@148.42,117.05 148.42,116.18 157.5,107.1 157.5,101.777 166.1,93.177 166.1,92.633 166.483,92.25 DD1.145@166.9,92.25
  Bottom Layer w0.15: VD48A.3@148.437,115.5 148.437,116.587 JA.58@148.6,116.75
A48: DD1.146 JA.59 VD47A.3 | length 38.2
  Top Layer w0.15: JA.59@145.88,119.59 147.2,118.27 147.2,116.35 157.2,106.35 157.2,101.653 165.8,93.053 165.8,92.433 166.533,91.7 DD1.146@166.75,91.7
  Bottom Layer w0.15: JA.59@145.8,119.7 145.9,119.8 VD47A.3@145.9,121.2
A49: DD1.147 JA.60 VD46A.3 | length 35.6
  Top Layer w0.15: JA.60@145.88,117.05 145.88,116.97 156.9,105.95 156.9,101.529 165.5,92.929 165.5,92.233 166.533,91.2 DD1.147@166.75,91.2
  Bottom Layer w0.15: VD46A.3@145.9,115.5 JA.60@145.9,116.5
A50: DD1.148 JA.63 VD65A.3 | length 43.7
  Top Layer w0.15: JA.63@140.8,119.59 142.05,118.34 142.05,115.8 142.6,115.25 147.05,115.25 156.6,105.7 156.6,101.404 165.2,92.804 165.2,92.033 166.533,90.7 DD1.148@166.8,90.7
  Bottom Layer w0.15: JA.63@140.8,119.95 VD65A.3@140.8,121.2
A51: DD1.159 JA.64 VD64A.3 | length 47.5
  Top Layer w0.15: JA.64@140.8,117.05 140.8,116.3 142.4,114.7 147.05,114.7 156.3,105.45 156.3,101.28 163.275,94.305 163.275,86.825 164.95,85.15 DD1.159@166.55,85.15
  Bottom Layer w0.15: JA.64@140.75,116.75 140.8,116.7 VD64A.3@140.8,115.5
A52: DD1.160 JA.65 VD63A.3 | length 52.2
  Top Layer w0.15: JA.65@138.26,119.59 139.5,118.35 139.5,115.7 140.9,114.3 146.75,114.3 156,105.05 156,101.156 162.975,94.181 162.975,86.701 164.976,84.7 DD1.160@166.5,84.7
  Bottom Layer w0.15: JA.65@138.25,119.95 138.3,120 VD63A.3@138.3,121.2
A53: DD1.161 JA.66 VD62A.3 | length 50.5
  Top Layer w0.15: JA.66@138.26,117.05 138.26,115.29 139.9,113.65 146.55,113.65 155.7,104.5 155.7,101.032 162.675,94.057 162.675,86.576 165.051,84.2 DD1.161@166.5,84.2
  Bottom Layer w0.15: VD62A.3@138.262,115.5 138.262,116.512 JA.66@138.4,116.65
A54: DD1.162 JA.67 VD61A.3 | length 55.4
  Top Layer w0.15: JA.67@135.72,119.59 137.05,118.26 137.05,115.2 139,113.25 146.35,113.25 155.4,104.2 155.4,100.907 162.375,93.932 162.375,86.452 165.127,83.7 DD1.162@166.5,83.7
  Bottom Layer w0.15: VD61A.3@135.75,121.2 135.75,119.7 JA.67@135.85,119.6
A55: DD1.164 JA.68 VD60A.3 | length 53.3
  Top Layer w0.15: JA.68@135.72,117.05 135.72,115.43 138.25,112.9 146.249,112.9 155.1,104.049 155.1,100.783 162.075,93.808 162.075,86.328 165.753,82.65 DD1.164@166.55,82.65
  Bottom Layer w0.15: VD60A.3@135.725,115.5 135.725,116.325 JA.68@135.8,116.4
A56: DD1.166 JA.69 VD59A.3 | length 58.3
  Top Layer w0.15: JA.69@133.18,119.59 134.45,118.32 134.45,116.204 138.054,112.6 146.124,112.6 154.8,103.924 154.8,100.659 161.775,93.684 161.775,86.204 166.279,81.7 DD1.166@166.75,81.7
  Bottom Layer w0.15: VD59A.3@133.2,121.2 133.2,119.85 JA.69@133.3,119.75
A57: DD1.167 JA.70 VD58A.3 | length 55.7
  Top Layer w0.15: JA.70@133.18,117.05 137.93,112.3 146,112.3 154.5,103.8 154.5,100.535 161.475,93.56 161.475,86.079 166.354,81.2 DD1.167@166.5,81.2
  Bottom Layer w0.15: VD58A.3@133.187,115.5 133.187,116.587 JA.70@133.3,116.7
A58: DD1.168 JA.71 VD57A.3 | length 60.8
  Top Layer w0.15: JA.71@130.64,119.59 131.95,118.28 131.95,116.164 136.114,112 145.876,112 154.2,103.676 154.2,100.41 161.175,93.435 161.175,85.955 166.43,80.7 DD1.168@166.5,80.7
  Bottom Layer w0.15: JA.71@130.55,119.95 130.6,120 VD57A.3@130.6,121.2
A59: DD1.169 JA.72 VD56A.3 | length 58.7
  Top Layer w0.15: JA.72@130.64,117.05 135.99,111.7 145.751,111.7 153.9,103.551 153.9,100.286 160.875,93.311 160.875,85.825 DD1.169@166.45,80.25
  Bottom Layer w0.15: VD56A.3@130.65,115.5 130.65,116.55 JA.72@130.85,116.75
ASD: DD1.12 DD2.15 DD3.6 X2.9 | length 57.3
  Top Layer w0.15: DD3.6@194.825,83 195.55,83 195.7,83.15 196.55,83.15 v1@196.65,83.25 ; v1(198.15,81.05) 198.993,80.207 DD1.12@201.006,80.207 203.507,80.207 203.95,80.65 207.55,80.65 207.993,80.207 215.057,80.207 221.45,86.6 221.45,96.1 v1(223.05,97.7)
  Bottom Layer w0.15: v1(196.7,83.25) 197.3,83.25 197.625,82.925 197.625,81.575 v1@198.05,81.15 ; DD2.15@206.1,87.175 207.175,87.175 207.65,86.7 v1@207.65,80.7 ; X2.9@221.7,103 221.75,103 223.45,101.3 223.45,100.15 223.05,99.75 v1(223.05,97.7)
  other v1: 207.65,80.65
B0: DD1.93 DD3.73 JB.3 VD15B.3 | length 101.7
  Top Layer w0.15: JB.3@128.59,59.05 127.35,60.29 127.35,62.25 133.565,68.465 155.365,68.465 156.3,69.4 v1@156.3,70.65 ; DD3.73@173.775,98 v1(181.95,98) ; v1@181.8,103.6 182.1,103.9 182.1,104.7 182.906,105.506 DD1.93@182.906,106.307
  Bottom Layer w0.15: v1(156.25,70.8) 156.55,70.5 170.058,70.5 176.875,77.317 176.875,84.258 178.7,86.083 178.7,89.95 181.675,92.925 181.675,103.425 v1(181.85,103.6)
  Bottom Layer w0.3: JB.3@128.45,58.95 128.55,58.85 VD15B.3@128.55,57.45
B1: DD1.94 DD3.74 JB.4 VD14B.3 | length 96
  Top Layer w0.15: JB.4@128.59,61.59 135.165,68.165 155.489,68.165 157,69.675 v1(157,71.05) ; DD3.74@173.775,97.5 176.823,97.5 v1@181.2,97.5 ; v1@181.5,104.4 181.5,104.6 182.406,105.506 DD1.94@182.406,106.307
  Bottom Layer w0.15: v1(157,71.05) 157.25,70.8 169.933,70.8 176.575,77.442 176.575,84.382 178.4,86.207 178.4,90.113 181.1,92.813 181.1,98.7 181.325,98.925 181.325,104.175 v1(181.55,104.4)
  Bottom Layer w0.3: JB.4@128.35,61.6 128.6,61.85 VD14B.3@128.6,63.2
  other v1: 181.1,97.45
B2: DD1.95 DD3.75 JB.5 VD13B.3 | length 99.9
  Top Layer w0.15: JB.5@131.13,59.05 129.95,60.23 129.95,62.25 135.565,67.865 155.765,67.865 157.525,69.625 157.525,71.267 157.217,71.575 156.275,71.575 v1(156.25,71.55) ; DD3.75@173.775,97 180.449,97 v1(180.55,96.9) ; v1@180.7,104.95 181.4,104.95 181.906,105.456 DD1.95@181.906,106.307
  Bottom Layer w0.15: v1@156.525,71.575 157.217,71.575 157.692,71.1 169.809,71.1 176.275,77.566 176.275,84.507 178.1,86.332 178.1,90.238 180.55,92.688 180.55,98.574 181.025,99.049 181.025,104.775 v1(180.9,104.9)
  Bottom Layer w0.3: JB.5@130.95,58.85 131.1,58.7 VD13B.3@131.1,57.45
B3: DD1.98 DD3.76 JB.6 VD12B.3 | length 94
  Top Layer w0.15: JB.6@131.13,61.59 137.105,67.565 156.088,67.565 158.05,69.527 158.05,71.166 157.116,72.1 v1(157.05,72.1) ; DD3.76@173.775,96.5 176.974,96.5 v1@179.925,96.5 ; v1@180.1,104.9 180.4,105.2 180.4,105.533 180.406,105.526 DD1.98@180.406,106.307
  Bottom Layer w0.15: v1@157.05,72.258 157.908,71.4 169.685,71.4 175.975,77.69 175.975,84.631 177.8,86.456 177.8,90.362 180,92.562 180,98.449 180.725,99.173 180.725,103.975 180.15,104.55 v1(180.15,104.9)
  Bottom Layer w0.3: VD12B.3@131.137,63.2 131.137,61.863 JB.6@131.45,61.55
  other v1: 180,96.35
B4: DD1.99 DD3.77 JB.7 VD11B.3 | length 95.2
  Top Layer w0.15: JB.7@133.67,59.05 132.4,60.32 132.4,62.3 137.365,67.265 156.212,67.265 158.4,69.453 158.4,71.65 157.95,72.1 v1@157.8,72.1 ; DD3.77@173.775,96 173.825,96.05 179.15,96.05 179.4,95.8 v1@179.4,95.75 ; v1@179.75,104.1 179.75,104.2 179.45,104.5 179.45,105.05 179.906,105.506 DD1.99@179.906,106.307
  Bottom Layer w0.15: v1@157.8,72.1 157.95,72.1 158.35,71.7 169.56,71.7 175.675,77.815 175.675,84.755 177.5,86.58 177.5,90.486 179.45,92.436 179.45,98.323 180.425,99.297 180.425,103.475 179.65,104.25 v1(179.65,104.3)
  Bottom Layer w0.3: JB.7@133.5,59.15 133.65,59 VD11B.3@133.65,57.45
  other v1: 157.8,72.25 179.45,95.75
B5: DD1.100 DD3.79 JB.8 VD10B.3 | length 90.4
  Top Layer w0.15: JB.8@133.67,61.59 139.045,66.965 156.336,66.965 158.75,69.379 158.75,72.05 v1(157.8,73) v1@157.75,73 ; DD3.79@173.775,95 173.825,94.95 175.45,94.95 175.75,95.25 v1(178.85,95.25) ; DD1.100@179.425,106.288 DD1.100@179.406,106.307 179.406,105.506 179.125,105.225 179.125,104.025 v1@179.7,103.45
  Bottom Layer w0.15: v1(157.8,73) 158.8,72 169.436,72 175.375,77.939 175.375,84.879 177.2,86.704 177.2,90.61 178.85,92.26 178.85,98.15 180.125,99.425 180.125,102.592 179.75,102.967 v1(179.75,103.4)
  Bottom Layer w0.3: JB.8@133.55,61.7 133.675,61.825 VD10B.3@133.675,63.2
B6: DD1.101 DD3.80 JB.9 VD9B.3 | length 90.7
  Top Layer w0.15: JB.9@136.21,59.05 134.9,60.36 134.9,62.1 139.465,66.665 156.461,66.665 159.1,69.304 159.1,72.5 v1@158.55,73.05 ; DD3.80@173.775,94.5 173.825,94.55 v1@178.3,94.55 ; v1@178.85,103.5 178.7,103.65 178.7,105.3 178.906,105.506 DD1.101@178.906,106.307
  Bottom Layer w0.15: v1@158.55,73.05 159.3,72.3 169.312,72.3 175.075,78.063 175.075,85.004 176.9,86.829 176.9,90.735 178.3,92.135 ; 178.3,92.15 v1(178.3,94.5) 178.3,98.024 179.825,99.549 179.825,102.467 179,103.292 v1(179,103.4)
  Bottom Layer w0.3: VD9B.3@136.2,57.45 JB.9@136.2,59.05
  other v1: 158.55,73
B7: DD1.102 DD3.83 JB.10 VD8B.3 | length 86.4
  Top Layer w0.15: JB.10@136.21,61.59 136.34,61.59 141.115,66.365 156.585,66.365 159.4,69.18 159.4,72.9 v1@158.5,73.8 ; DD3.83@173.775,93 174.55,93 174.775,92.775 175.267,92.775 175.642,93.15 v1@177.75,93.15 ; DD1.102@178.406,106.307 178.4,106.3 178.4,103.25 v1@179.3,102.35
  Bottom Layer w0.15: v1@158.55,73.8 159.75,72.6 169.188,72.6 174.775,78.187 174.775,85.128 176.6,86.953 176.6,90.859 177.75,92.009 177.75,97.899 179.3,99.448 v1(179.3,102.25)
  Bottom Layer w0.3: JB.10@136.2,61.65 136.212,61.662 VD8B.3@136.212,63.2
  other v1: 158.55,73.75 177.75,93.1
B8: DD1.103 DD3.84 JB.11 VD7B.3 | length 88.7
  Top Layer w0.15: JB.11@138.75,59.05 137.5,60.3 137.5,62.326 141.239,66.065 156.709,66.065 159.7,69.056 159.7,73.35 v1@158.65,74.4 ; DD3.84@173.775,92.5 174.45,92.5 174.6,92.35 175.267,92.35 175.742,92.825 176.775,92.825 v1@177.2,92.4 ; DD1.103@177.906,106.307 177.906,103.285 178.75,102.442 v1@178.75,101.85
  Bottom Layer w0.15: v1@158.6,74.45 160.15,72.9 169.063,72.9 174.475,78.312 174.475,85.252 176.3,87.077 176.3,90.983 177.2,91.883 177.2,97.773 178.75,99.322 v1(178.75,101.7)
  Bottom Layer w0.3: VD7B.3@138.75,57.45 138.75,58.95 JB.11@138.8,59
  other v1: 158.55,74.5 177.2,92.5
B9: DD1.106 DD3.85 JB.12 VD6B.3 | length 83.1
  Top Layer w0.15: JB.12@138.75,61.59 142.925,65.765 156.833,65.765 160,68.932 160,73.7 159.25,74.45 v1(159.25,74.85) ; DD3.85@173.775,92 175.4,92 175.7,92.3 v1(176.4,92.3) ; DD1.106@176.406,106.307 176.406,104.11 178.15,102.366 v1@178.15,102.3
  Bottom Layer w0.15: v1@159.25,74.9 159.25,74.457 160.507,73.2 168.939,73.2 174.175,78.436 174.175,85.376 176,87.201 176,91.108 176.4,91.508 176.4,92.85 176.9,93.35 176.9,97.897 178.2,99.197 v1(178.2,102.25)
  Bottom Layer w0.3: JB.12@138.7,61.7 138.75,61.75 VD6B.3@138.75,63.2
B10: DD1.107 DD3.86 JB.15 VD25B.3 | length 79.6
  Top Layer w0.15: JB.15@143.83,59.05 142.65,60.23 142.65,62.45 143.4,63.2 145.665,65.465 156.958,65.465 160.3,68.807 160.3,74.15 v1(159.95,74.5) ; DD3.86@173.775,91.5 173.825,91.55 175.65,91.55 v1@175.8,91.7 ; DD1.107@175.906,106.307 175.906,104.186 177.65,102.442 v1(177.65,101.7)
  Bottom Layer w0.15: v1@160,74.4 160.9,73.5 168.815,73.5 173.875,78.56 173.875,85.501 175.7,87.326 175.7,92.576 176.6,93.476 176.6,98.021 177.65,99.071 v1(177.65,101.7)
  Bottom Layer w0.3: JB.15@143.75,58.55 143.85,58.45 VD25B.3@143.85,57.45
  other v1: 175.85,91.7
B11: DD1.108 DD3.87 JB.16 VD24B.3 | length 75.4
  Top Layer w0.15: JB.16@143.83,61.59 147.405,65.165 157.082,65.165 160.6,68.683 160.6,74.65 v1@159.975,75.275 ; DD3.87@173.775,91 174.8,91 v1@174.85,91.05 ; DD1.108@175.406,106.307 175.406,104.144 177.05,102.5 v1@177.05,102.3
  Bottom Layer w0.15: v1@160,75.25 161.45,73.8 168.685,73.8 173.575,78.69 173.575,85.625 175.375,87.425 175.375,89.667 175,90.042 v1@175,90.9 ; v1(174.95,91) 174.95,92.25 176.3,93.6 176.3,98.146 177.1,98.945 v1(177.1,102.25)
  Bottom Layer w0.3: JB.16@143.75,61.6 143.85,61.7 VD24B.3@143.85,63.2
  other v1: 159.95,75.25
B12: DD1.109 JB.17 VD23B.3 | length 74.8
  Top Layer w0.15: JB.17@146.37,59.05 145.1,60.32 145.1,62.25 147.715,64.865 157.206,64.865 160.9,68.559 160.9,75.1 v1@160.725,75.275 ; DD1.109@174.906,106.307 174.906,103.844 v1(175.9,102.85)
  Bottom Layer w0.15: v1(160.7,75.3) 161.9,74.1 168.561,74.1 173.275,78.814 173.275,100.102 175.9,102.727 v1(175.9,102.85)
  Bottom Layer w0.3: JB.17@146.05,59.2 146.387,58.863 VD23B.3@146.387,57.45
B13: DD1.110 JB.18 VD22B.3 | length 70.3
  Top Layer w0.15: JB.18@146.37,61.59 146.44,61.59 149.415,64.565 157.33,64.565 161.225,68.46 161.225,75.525 v1(160.7,76.05) ; DD1.110@174.406,106.307 174.406,103.594 v1@175.15,102.85
  Bottom Layer w0.15: v1(160.7,76.05) 160.75,76.05 162.4,74.4 168.436,74.4 172.975,78.939 172.975,100.625 v1(175.15,102.8)
  Bottom Layer w0.3: VD22B.3@146.387,63.2 146.387,61.763 JB.18@146.4,61.75
B14: DD1.111 DD3.98 JB.19 VD21B.3 | length 76.2
  Top Layer w0.15: JB.19@148.91,59.05 147.7,60.26 147.7,62.3 149.665,64.265 157.455,64.265 161.525,68.335 161.525,75.967 160.192,77.3 v1@160.15,77.3 ; v1@172.45,85.1 172.85,85.5 DD3.98@173.775,85.5 ; DD1.111@173.906,106.307 173.906,103.344 v1@174.5,102.75
  Bottom Layer w0.15: v1@160.2,77.35 162.85,74.7 168.312,74.7 172.675,79.063 172.675,101.025 174.4,102.75 v1(174.4,102.8)
  Bottom Layer w0.3: JB.19@148.9,58.9 148.925,58.875 VD21B.3@148.925,57.45
  other v1: 160.15,77.4 172.4,85.05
